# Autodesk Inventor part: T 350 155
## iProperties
Company: Mayer & Müller AG Schaltgeräte
Created: 2005-06
Part Number: T 350 155
Material: Ag-Ni85/15
Description: Edelmetallplatte
Document SubType Name: Modeling
Designer: I.Baliuc
Manufacturer: Standard
Standards Organization: Custom
Density: 9.7 g/cm^3
Author: T.Messerschmitt
Revision Number: 350155
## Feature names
1. Extrusion1
2. Extrusion4
3. Rechteckige Anordnung5 [Rectangular Pattern]
4. Rechteckige Anordnung6 [Rectangular Pattern]
